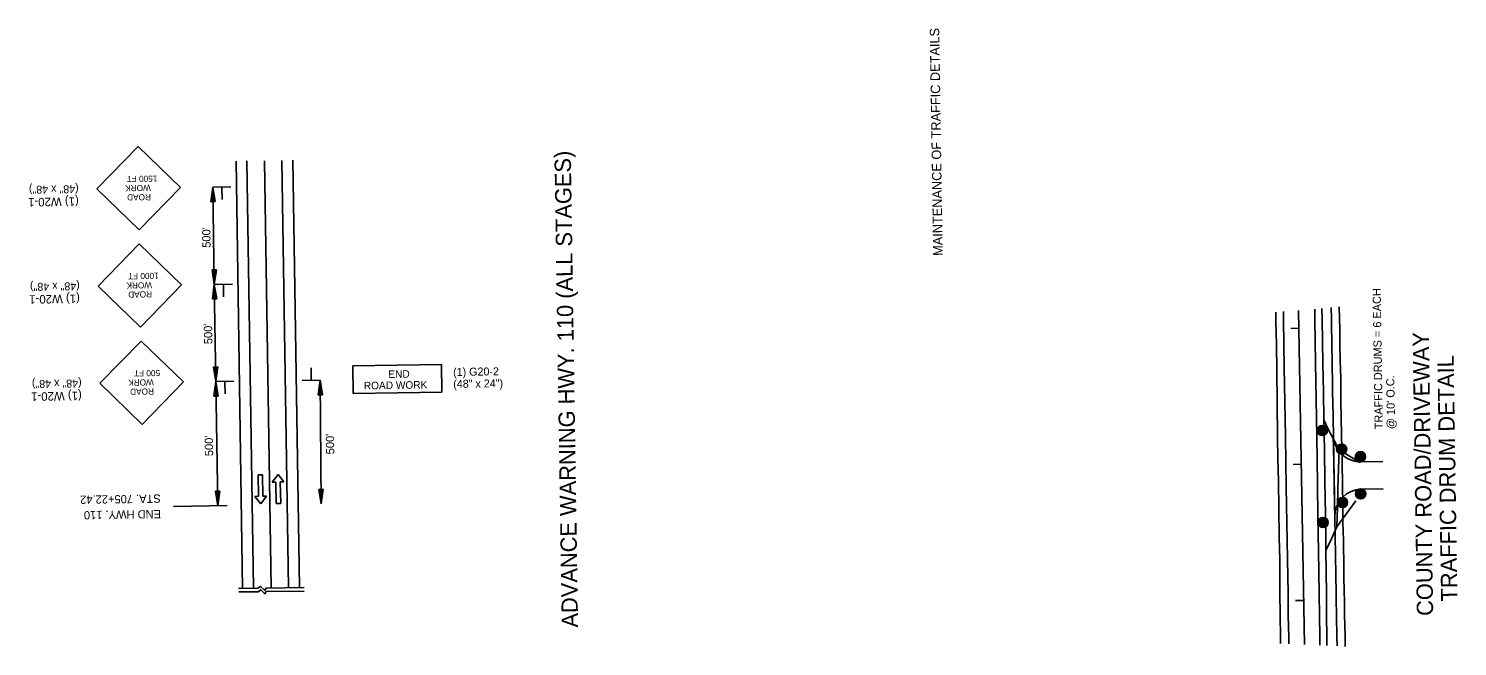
# Model space of a CAD drawing. Extents: x 1770139 to 1773492, y 718230 to 727190.
# Drawn here: x 1770380 to 1771430, y 721548 to 722002 of the extents above; entities that cross this region are included whole.
import ezdxf

# ---------------------------------------------------------------- set-up
doc = ezdxf.new("R2010")
doc.units = 0
for name, color, linetype in [('Default', 7, 'Continuous'), ('R_Border', 7, 'Continuous'), ('R_Dimension', 7, 'Continuous'), ('R_Draft', 7, 'Continuous'), ('R_Drive', 7, 'Continuous'), ('R_Horz Alg', 7, 'Continuous'), ('R_MOT', 7, 'Continuous'), ('R_Proposed Road', 7, 'Continuous')]:
    doc.layers.add(name, color=color, linetype=linetype)

msp = doc.modelspace()

# ---------------------------------------------------------------- linework, layer by layer
at = {"layer": 'Default'}
for p, q in [((1770540.7, 721904.5), (1770545.5, 721590.6)), ((1770553.5, 721904.7), (1770558.4, 721590.8)), ((1770566.4, 721904.9), (1770571.2, 721590.9)), ((1770515.6, 721885.3), (1770516.7, 721813.8)), ((1770516.7, 721813.8), (1770517.8, 721742.4)), ((1770595.1, 721652.5), (1770594.5, 721743.4)), ((1770517.8, 721742.4), (1770519.2, 721651.2)), ((1771334.4, 721707.4), (1771327.2, 721707.3)), ((1771334.5, 721705.4), (1771327.2, 721705.3)), ((1771348.6, 721693.8), (1771341.4, 721693.7)), ((1771348.6, 721691.8), (1771341.4, 721691.7)), ((1771362.4, 721688.2), (1771355.2, 721688.1)), ((1771362.4, 721686.2), (1771355.2, 721686.1)), ((1770549, 721673.8), (1770552.2, 721673.9)), ((1770549.2, 721658.1), (1770549, 721673.8)), ((1770552.4, 721658.1), (1770552.2, 721673.9)), ((1770559.3, 721668.6), (1770563.5, 721674.2)), ((1770563.5, 721674.2), (1770567.9, 721668.7)), ((1770559.3, 721668.6), (1770562, 721668.6)), ((1770562, 721668.6), (1770562.2, 721652.9)), ((1770565.2, 721668.7), (1770565.5, 721652.9)), ((1770565.2, 721668.7), (1770567.9, 721668.7)), ((1771362.6, 721660.9), (1771355.3, 721660.8)), ((1770486.8, 721650.7), (1770526.1, 721651.3)), ((1770546.5, 721658), (1770549.2, 721658.1)), ((1770546.5, 721658), (1770550.9, 721652.5)), ((1770550.9, 721652.5), (1770555.1, 721658.2)), ((1770552.4, 721658.1), (1770555.1, 721658.2)), ((1770562.2, 721652.9), (1770565.5, 721652.9)), ((1771349.2, 721654.6), (1771342, 721654.5)), ((1771349.3, 721652.6), (1771342, 721652.5)), ((1771362.6, 721658.9), (1771355.4, 721658.8)), ((1771335, 721639.8), (1771327.8, 721639.7)), ((1771335, 721637.8), (1771327.8, 721637.7)), ((1770534.5, 721590.4), (1770548.7, 721590.6)), ((1770534.8, 721587.8), (1770549, 721588)), ((1770554.6, 721590.7), (1770582.7, 721591.1)), ((1770554.8, 721588.1), (1770582.7, 721588.5))]:
    msp.add_line(p, q, dxfattribs=at)
for points in [[(1771329, 721548.6), (1771328.9, 721554.6), (1771328.7, 721570.6), (1771328.5, 721586.6), (1771328.2, 721602.3), (1771328, 721618.1), (1771327.6, 721642.7), (1771327.3, 721667.3), (1771327, 721684.6), (1771326.8, 721701.9), (1771326.6, 721715.5), (1771326.3, 721729.1), (1771326.1, 721742.7), (1771325.9, 721756.2), (1771325.6, 721772.3), (1771325.3, 721788.4), (1771325.2, 721795.7)], [(1771334.2, 721548.4), (1771334.2, 721554.7), (1771334, 721570.7), (1771333.8, 721586.7), (1771333.7, 721602.7), (1771333.5, 721618.6), (1771333.3, 721631.3), (1771333.1, 721644), (1771332.8, 721656.7), (1771332.6, 721669.3), (1771332.3, 721691.9), (1771332, 721714.4), (1771331.6, 721734.9), (1771331.2, 721755.5), (1771330.9, 721771.8), (1771330.6, 721788.2), (1771330.4, 721796.1)], [(1771300.2, 721549.9), (1771300.1, 721554.6), (1771299.9, 721570.8), (1771299.7, 721586.9), (1771299.5, 721611.3), (1771299, 721628.2), (1771298.8, 721648.8), (1771298.5, 721669.4), (1771298.2, 721685.6), (1771297.8, 721701.7), (1771297.6, 721726.5), (1771297.4, 721751.3), (1771297.1, 721769.1), (1771296.7, 721786.8), (1771296.6, 721793.3)], [(1771306.2, 721549.7), (1771306.1, 721554.5), (1771305.8, 721570.6), (1771305.6, 721586.8), (1771305.4, 721599.4), (1771305.2, 721612), (1771305, 721625.2), (1771304.7, 721638.5), (1771304.5, 721651.7), (1771304.3, 721664.9), (1771304, 721683.5), (1771303.7, 721702.1), (1771303.5, 721714.7), (1771303.3, 721727.3), (1771303.1, 721739.9), (1771302.9, 721752.5), (1771302.6, 721769.8), (1771302.3, 721787.1), (1771302.2, 721793.8)], [(1771334.8, 721707.9), (1771332, 721714.4)], [(1771336.5, 721624.6), (1771341.5, 721635.6), (1771341.9, 721649.8), (1771342.3, 721663.9), (1771342.7, 721678), (1771343.1, 721692.2), (1771334.8, 721707.9)], [(1771358.3, 721682.9), (1771343.1, 721692.2)], [(1771341.5, 721635.6), (1771355.4, 721654.7)], [(1771333.5, 721618.6), (1771336.5, 721624.6)], [(1770554.6, 721590.7), (1770553.7, 721589), (1770550.6, 721591.9), (1770548.7, 721590.6)], [(1770554.8, 721588.1), (1770553.9, 721586.5), (1770550.8, 721589.4), (1770549, 721588)]]:
    msp.add_lwpolyline(points, dxfattribs=at)
for centre, radius in [((1771330.8, 721706.4), 3.75), ((1771330.8, 721706.4), 3.4), ((1771330.8, 721706.4), 2.9), ((1771330.8, 721706.4), 2.4), ((1771330.8, 721706.4), 1.9), ((1771330.8, 721706.4), 1.4), ((1771330.8, 721706.4), 0.898), ((1771330.8, 721706.4), 0.398), ((1771345, 721692.7), 3.75), ((1771345, 721692.7), 3.4), ((1771345, 721692.7), 2.9), ((1771345, 721692.7), 2.4), ((1771345, 721692.7), 1.9), ((1771345, 721692.7), 1.4), ((1771345, 721692.7), 0.898), ((1771345, 721692.7), 0.398), ((1771358.8, 721687.2), 3.75), ((1771358.8, 721687.2), 3.4), ((1771358.8, 721687.2), 2.9), ((1771358.8, 721687.2), 2.4), ((1771358.8, 721687.2), 1.9), ((1771358.8, 721687.2), 1.4), ((1771358.8, 721687.2), 0.898), ((1771358.8, 721687.2), 0.398), ((1771359, 721659.9), 3.75), ((1771359, 721659.9), 3.4), ((1771359, 721659.9), 2.9), ((1771359, 721659.9), 2.4), ((1771359, 721659.9), 1.9), ((1771359, 721659.9), 1.4), ((1771359, 721659.9), 0.898), ((1771359, 721659.9), 0.398), ((1771345.6, 721653.5), 3.75), ((1771345.6, 721653.5), 3.4), ((1771345.6, 721653.5), 2.9), ((1771345.6, 721653.5), 2.4), ((1771345.6, 721653.5), 1.9), ((1771345.6, 721653.5), 1.4), ((1771345.6, 721653.5), 0.898), ((1771345.6, 721653.5), 0.398), ((1771331.4, 721638.8), 3.75), ((1771331.4, 721638.8), 3.4), ((1771331.4, 721638.8), 2.9), ((1771331.4, 721638.8), 2.4), ((1771331.4, 721638.8), 1.9), ((1771331.4, 721638.8), 1.4), ((1771331.4, 721638.8), 0.898), ((1771331.4, 721638.8), 0.398)]:
    msp.add_circle(centre, radius, dxfattribs=at)
at = {"layer": 'R_Dimension'}
for p, q in [((1770532.7, 721904.4), (1770537.5, 721590.4)), ((1770574.4, 721905), (1770579.2, 721591.1))]:
    msp.add_line(p, q, dxfattribs=at)
at = {"layer": 'R_Draft'}
for p, q in [((1770514.2, 721874.5), (1770515.6, 721885.3)), ((1770514.5, 721874.5), (1770515.7, 721883.5)), ((1770514.7, 721874.5), (1770515.7, 721881.6)), ((1770515, 721874.5), (1770515.7, 721879.8)), ((1770517.4, 721874.6), (1770515.6, 721885.3)), ((1770517.1, 721874.6), (1770515.7, 721883.5)), ((1770516.9, 721874.6), (1770515.7, 721881.6)), ((1770516.6, 721874.6), (1770515.7, 721879.8)), ((1770514.2, 721874.5), (1770517.4, 721874.6)), ((1770515.3, 721874.5), (1770515.8, 721878)), ((1770515.6, 721874.5), (1770515.8, 721876.2)), ((1770516.3, 721874.6), (1770515.8, 721878)), ((1770516.1, 721874.6), (1770515.8, 721876.2)), ((1770518.2, 721824.6), (1770515, 721824.5)), ((1770515, 721824.5), (1770516.7, 721813.8)), ((1770515.2, 721824.5), (1770516.7, 721815.6)), ((1770515.5, 721824.5), (1770516.7, 721817.5)), ((1770515.8, 721824.5), (1770516.7, 721819.3)), ((1770516.1, 721824.5), (1770516.6, 721821.1)), ((1770516.3, 721824.6), (1770516.6, 721822.9)), ((1770517.1, 721824.6), (1770516.6, 721821.1)), ((1770516.8, 721824.6), (1770516.6, 721822.9)), ((1770518.2, 721824.6), (1770516.7, 721813.8)), ((1770517.6, 721824.6), (1770516.7, 721817.5)), ((1770517.9, 721824.6), (1770516.7, 721815.6)), ((1770517.4, 721824.6), (1770516.7, 721819.3)), ((1770515.3, 721803.1), (1770516.7, 721813.8)), ((1770515.6, 721803.1), (1770516.8, 721812.1)), ((1770515.8, 721803.1), (1770516.8, 721810.2)), ((1770516.1, 721803.1), (1770516.8, 721808.4)), ((1770516.4, 721803.1), (1770516.9, 721806.6)), ((1770518.5, 721803.2), (1770516.7, 721813.8)), ((1770518.2, 721803.2), (1770516.8, 721812.1)), ((1770518, 721803.1), (1770516.8, 721810.2)), ((1770517.7, 721803.1), (1770516.8, 721808.4)), ((1770517.4, 721803.1), (1770516.9, 721806.6)), ((1770515.3, 721803.1), (1770518.5, 721803.2)), ((1770516.7, 721803.1), (1770516.9, 721804.8)), ((1770517.2, 721803.1), (1770516.9, 721804.8)), ((1770519.3, 721753.2), (1770516.1, 721753.1)), ((1770516.1, 721753.1), (1770517.8, 721742.4)), ((1770516.3, 721753.1), (1770517.8, 721744.2)), ((1770516.6, 721753.1), (1770517.8, 721746.1)), ((1770516.9, 721753.1), (1770517.8, 721747.8)), ((1770517.2, 721753.1), (1770517.7, 721749.7)), ((1770517.4, 721753.1), (1770517.7, 721751.4)), ((1770518.2, 721753.1), (1770517.7, 721749.7)), ((1770517.9, 721753.1), (1770517.7, 721751.4)), ((1770519.3, 721753.2), (1770517.8, 721742.4)), ((1770518.7, 721753.2), (1770517.8, 721746.1)), ((1770519, 721753.2), (1770517.8, 721744.2)), ((1770518.5, 721753.1), (1770517.8, 721747.8)), ((1770593, 721732.7), (1770594.5, 721743.4)), ((1770596.2, 721732.7), (1770594.5, 721743.4)), ((1770516.4, 721731.7), (1770517.8, 721742.4)), ((1770516.7, 721731.7), (1770517.9, 721740.6)), ((1770516.9, 721731.7), (1770517.9, 721738.8)), ((1770517.2, 721731.7), (1770517.9, 721737)), ((1770517.5, 721731.7), (1770518, 721735.2)), ((1770519.6, 721731.7), (1770517.8, 721742.4)), ((1770517.8, 721731.7), (1770518, 721733.4)), ((1770519.3, 721731.7), (1770517.9, 721740.6)), ((1770519.1, 721731.7), (1770517.9, 721738.8)), ((1770518.8, 721731.7), (1770517.9, 721737)), ((1770518.5, 721731.7), (1770518, 721735.2)), ((1770518.3, 721731.7), (1770518, 721733.4)), ((1770593, 721732.7), (1770596.2, 721732.7)), ((1770593.3, 721732.7), (1770594.5, 721741.6)), ((1770593.5, 721732.7), (1770594.5, 721739.8)), ((1770593.8, 721732.7), (1770594.6, 721738)), ((1770594.1, 721732.7), (1770594.6, 721736.2)), ((1770594.3, 721732.7), (1770594.6, 721734.4)), ((1770595.9, 721732.7), (1770594.5, 721741.6)), ((1770595.7, 721732.7), (1770594.5, 721739.8)), ((1770595.4, 721732.7), (1770594.6, 721738)), ((1770595.1, 721732.7), (1770594.6, 721736.2)), ((1770594.8, 721732.7), (1770594.6, 721734.4)), ((1770516.4, 721731.7), (1770519.6, 721731.7)), ((1770517.5, 721661.9), (1770519.2, 721651.2)), ((1770520.7, 721661.9), (1770517.5, 721661.9)), ((1770517.7, 721661.9), (1770519.2, 721653)), ((1770518, 721661.9), (1770519.2, 721654.8)), ((1770518.3, 721661.9), (1770519.2, 721656.6)), ((1770518.6, 721661.9), (1770519.1, 721658.4)), ((1770518.8, 721661.9), (1770519.1, 721660.2)), ((1770519.6, 721661.9), (1770519.1, 721658.4)), ((1770519.3, 721661.9), (1770519.1, 721660.2)), ((1770520.7, 721661.9), (1770519.2, 721651.2)), ((1770520.1, 721661.9), (1770519.2, 721654.8)), ((1770520.4, 721661.9), (1770519.2, 721653)), ((1770519.9, 721661.9), (1770519.2, 721656.6)), ((1770596.6, 721663.3), (1770593.4, 721663.2)), ((1770593.4, 721663.2), (1770595.1, 721652.5)), ((1770593.6, 721663.2), (1770595.1, 721654.3)), ((1770593.9, 721663.2), (1770595.1, 721656.2)), ((1770594.2, 721663.2), (1770595.1, 721658)), ((1770594.5, 721663.2), (1770595, 721659.8)), ((1770594.7, 721663.3), (1770595, 721661.6)), ((1770595.5, 721663.3), (1770595, 721659.8)), ((1770595.2, 721663.3), (1770595, 721661.6)), ((1770596.6, 721663.3), (1770595.1, 721652.5)), ((1770596, 721663.3), (1770595.1, 721656.2)), ((1770596.3, 721663.3), (1770595.1, 721654.3)), ((1770595.8, 721663.3), (1770595.1, 721658))]:
    msp.add_line(p, q, dxfattribs=at)
at = {"layer": 'R_Drive'}
for p, q in [((1771359.3, 721683.4), (1771375.3, 721683.6)), ((1771359.6, 721663.4), (1771375.6, 721663.6))]:
    msp.add_line(p, q, dxfattribs=at)
msp.add_lwpolyline([(1771340, 721643), (1771339.5, 721673), (1771338.9, 721703)], dxfattribs=at)
for centre, start, end in [((1771358.9, 721703.4), 180.9818, 270.9818), ((1771360, 721643.4), 90.9818, 180.9818)]:
    msp.add_arc(centre, 20, start, end, dxfattribs=at)
at = {"layer": 'R_Horz Alg'}
msp.add_line((1771313.4, 721794.7), (1771317.6, 721549.1), dxfattribs=at)
for points in [[(1771307.6, 721781.5), (1771313.6, 721781.6)], [(1771309.3, 721681.5), (1771315.3, 721681.6)], [(1771311, 721581.5), (1771317, 721581.6)]]:
    msp.add_lwpolyline(points, dxfattribs=at)
at = {"layer": 'R_MOT'}
for p, q in [((1770430.5, 721884), (1770460.7, 721915.1)), ((1770460.7, 721915.1), (1770491.8, 721884.9)), ((1770430.5, 721884), (1770461.6, 721853.8)), ((1770461.6, 721853.8), (1770491.8, 721884.9)), ((1770528.9, 721885.5), (1770515.6, 721885.3)), ((1770522.3, 721885.2), (1770522.4, 721876.1)), ((1770431.3, 721812.5), (1770461.5, 721843.6)), ((1770461.5, 721843.6), (1770492.6, 721813.5)), ((1770431.3, 721812.5), (1770462.4, 721782.4)), ((1770462.4, 721782.4), (1770492.6, 721813.5)), ((1770530, 721814), (1770516.7, 721813.8)), ((1770523.4, 721813.8), (1770523.5, 721804.7)), ((1770432.7, 721741.1), (1770462.9, 721772.2)), ((1770462.9, 721772.2), (1770494, 721742.1)), ((1770683.6, 721755), (1770618.5, 721754)), ((1770618.8, 721733.6), (1770618.5, 721754)), ((1770683.9, 721734.6), (1770683.6, 721755)), ((1770594.5, 721743.4), (1770581.3, 721743.2)), ((1770587.9, 721743.5), (1770587.8, 721752.5)), ((1770432.7, 721741.1), (1770463.8, 721710.9)), ((1770463.8, 721710.9), (1770494, 721742.1)), ((1770531.1, 721742.6), (1770517.8, 721742.4)), ((1770524.5, 721742.3), (1770524.6, 721733.3)), ((1770683.9, 721734.6), (1770618.8, 721733.6))]:
    msp.add_line(p, q, dxfattribs=at)
at = {"layer": 'R_Proposed Road'}
for points in [[(1771341.6, 721548.1), (1771341.5, 721554.8), (1771341.5, 721555.1), (1771341.2, 721570.8), (1771341.2, 721571.2), (1771341, 721582), (1771340.9, 721586.8), (1771340.9, 721587.4), (1771340.7, 721600), (1771340.7, 721602.5), (1771340.5, 721612.6), (1771340.4, 721618.3), (1771340.3, 721625.9), (1771340.2, 721632), (1771340, 721639.1), (1771340, 721642.9), (1771339.8, 721652.3), (1771339.6, 721665.5), (1771339.6, 721667.5), (1771339.3, 721682), (1771339.3, 721684.1), (1771339.3, 721684.8), (1771339, 721702.1), (1771339, 721702.7), (1771338.7, 721715.3), (1771338.7, 721715.7), (1771338.5, 721727.9), (1771338.5, 721729.3), (1771338.4, 721732), (1771338.3, 721740.5), (1771338.3, 721742.9), (1771338.1, 721753.1), (1771338, 721756.4), (1771337.8, 721770.4), (1771337.8, 721772.5), (1771337.6, 721782), (1771337.5, 721787.7), (1771337.5, 721788.6), (1771337.3, 721796.7)], [(1771347.6, 721547.8), (1771347.5, 721554.9), (1771347.5, 721555.2), (1771347.2, 721570.9), (1771347.2, 721571.3), (1771347, 721582.1), (1771346.9, 721586.9), (1771346.9, 721587.5), (1771346.7, 721600.1), (1771346.7, 721602.6), (1771346.5, 721612.7), (1771346.4, 721618.4), (1771346.3, 721626), (1771346.2, 721632.1), (1771346, 721639.2), (1771346, 721643), (1771345.8, 721652.4), (1771345.6, 721665.6), (1771345.6, 721667.6), (1771345.3, 721682.1), (1771345.3, 721684.2), (1771345.3, 721684.9), (1771345, 721702.2), (1771345, 721702.8), (1771344.7, 721715.4), (1771344.7, 721715.8), (1771344.5, 721728), (1771344.5, 721729.4), (1771344.4, 721732.1), (1771344.3, 721740.6), (1771344.3, 721743), (1771344.1, 721753.2), (1771344, 721756.6), (1771343.8, 721770.5), (1771343.8, 721772.6), (1771343.6, 721782.1), (1771343.5, 721787.8), (1771343.5, 721788.7), (1771343.3, 721797.2)]]:
    msp.add_lwpolyline(points, dxfattribs=at)

# ---------------------------------------------------------------- texts
at = {"layer": 'Default'}
for s, height, rotation, p in [("500'", 6.1, 90.8827, (1770514, 721840.7)), ('TRAFFIC DRUMS = 6 EACH', 6, 90.8827, (1771375.3, 721707.4)), ("500'", 6.1, 90.8827, (1770515.3, 721769.9)), ('COUNTY ROAD/DRIVEWAY', 12, 90.8827, (1771412.3, 721570.3)), ('TRAFFIC DRUM DETAIL', 12, 90.8827, (1771430.1, 721580.9)), ("@ 10' O.C.", 6, 90.8827, (1771384.3, 721707.5)), ("500'", 6.1, 90.8827, (1770515.9, 721687.6)), ("500'", 6.1, 90.8827, (1770604.9, 721689)), ('STA. 705+22.42', 6.1, 180.8827, (1770477.3, 721659.5)), ('END HWY. 110', 6.1, 180.8827, (1770477.5, 721648.1))]:
    msp.add_text(s, height=height, rotation=rotation, dxfattribs=at).set_placement(p)
at = {"layer": 'R_Border'}
msp.add_text('MAINTENANCE OF TRAFFIC DETAILS', height=7, rotation=90.8827, dxfattribs=at).set_placement((1771051.9, 721834.8))
at = {"layer": 'R_Draft'}
msp.add_text('ADVANCE WARNING HWY. 110 (ALL STAGES)', height=12, rotation=90.8827, dxfattribs=at).set_placement((1770784, 721561.7))
at = {"layer": 'R_MOT'}
for s, height, rotation, p in [('1500 FT', 4.52, 180.8833, (1770474.8, 721893.8)), ('(1) W20-1', 6.27, 180.8827, (1770417.1, 721877.8)), ('(48" x 48")', 5.88, 180.8827, (1770417, 721886.8)), ('WORK', 4.52, 180.8827, (1770470, 721887)), ('ROAD', 4.52, 180.8831, (1770470.1, 721880.2)), ('(48" x 48")', 5.88, 180.8827, (1770417.8, 721815.4)), ('1000 FT', 4.52, 180.8833, (1770475.8, 721822.4)), ('(1) W20-1', 6.27, 180.8827, (1770417.9, 721806.4)), ('WORK', 4.52, 180.8827, (1770470.9, 721815.5)), ('ROAD', 4.52, 180.8831, (1770470.9, 721808.8)), ('(48" x 48")', 5.88, 180.8827, (1770419.2, 721744)), ('WORK', 4.52, 180.8827, (1770472.2, 721744.1)), (' 500 FT', 4.52, 180.8833, (1770478.5, 721751)), ('END', 5.56, 0.8827, (1770644.6, 721745)), ('(1) G20-2', 5.88, 0.8827, (1770692.2, 721746.5)), ('(48" x 24")', 5.88, 0.8827, (1770692.3, 721737.7)), ('(1) W20-1', 6.27, 180.8827, (1770419.3, 721735)), ('ROAD', 4.52, 180.8831, (1770472.3, 721737.4)), ('ROAD WORK', 5.56, 0.8827, (1770626.6, 721736.6))]:
    msp.add_text(s, height=height, rotation=rotation, dxfattribs=at).set_placement(p)

doc.saveas('drawing.dxf')
